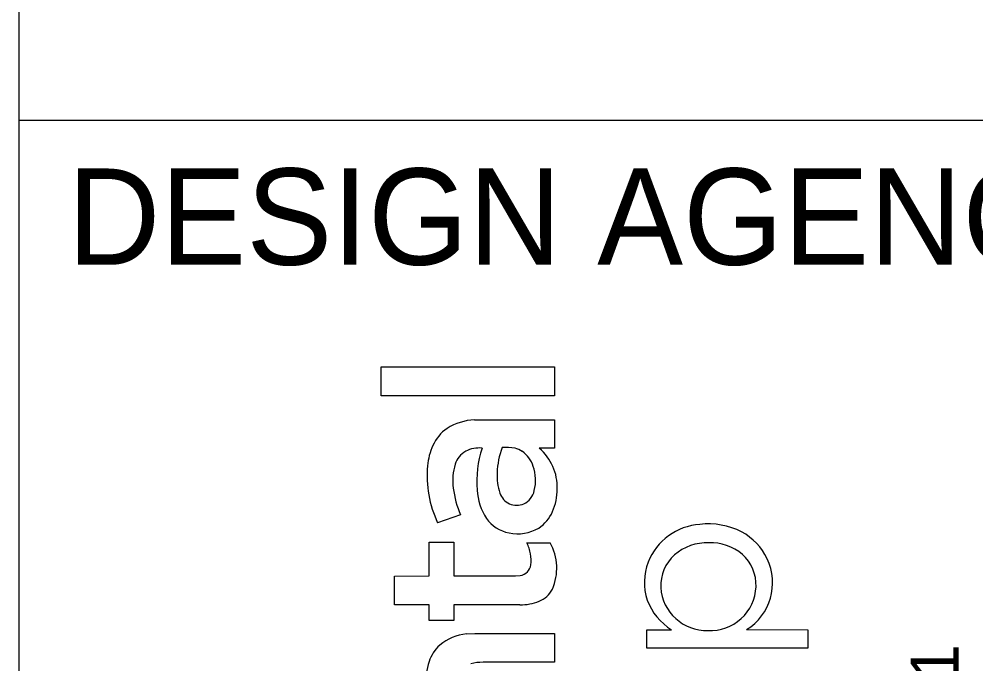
# Model space of a CAD drawing. Extents: x -6.7 to 34, y -1.6 to 22.
# Drawn here: x 32 to 32.993, y 4.436 to 5.105 of the extents above; entities that cross this region are included whole.
import ezdxf

# ---------------------------------------------------------------- set-up
doc = ezdxf.new("R2010")
doc.units = 0
doc.layers.add('SH_Border', color=7, linetype='Continuous')
doc.layers.add('SH_Cut_Line', color=7, linetype='Continuous')

msp = doc.modelspace()

# ---------------------------------------------------------------- linework, layer by layer
at = {"layer": 'SH_Border'}
for p, q in [((32, 0.5), (32, 21.5)), ((32, 5), (33.5, 5))]:
    msp.add_line(p, q, dxfattribs=at)
at = {"layer": 'SH_Cut_Line'}
for p, q in [((32.37557, 4.71411), (32.37557, 4.74397)), ((32.37557, 4.74397), (32.55571, 4.74397)), ((32.55571, 4.74397), (32.55571, 4.71411)), ((32.55571, 4.71411), (32.37557, 4.71411)), ((32.47265, 4.68899), (32.55553, 4.68918)), ((32.55553, 4.68918), (32.55571, 4.65956)), ((32.55571, 4.65956), (32.53971, 4.65956)), ((32.45818, 4.59045), (32.43431, 4.58233)), ((32.42542, 4.52705), (32.42548, 4.56209)), ((32.42548, 4.56209), (32.45108, 4.56209)), ((32.45108, 4.56209), (32.45117, 4.52705)), ((32.52695, 4.56159), (32.5511, 4.56159)), ((32.51498, 4.52705), (32.52005, 4.52749)), ((32.38964, 4.52701), (32.42542, 4.52705)), ((32.38964, 4.49719), (32.38964, 4.52701)), ((32.45117, 4.52705), (32.51498, 4.52705)), ((32.42542, 4.49717), (32.38964, 4.49719)), ((32.42542, 4.48067), (32.42542, 4.49717)), ((32.51969, 4.49718), (32.45108, 4.49715)), ((32.45108, 4.49715), (32.45108, 4.48066)), ((32.45108, 4.48066), (32.42542, 4.48067)), ((32.65152, 4.47113), (32.67709, 4.47115)), ((32.65152, 4.45215), (32.65152, 4.47113)), ((32.75491, 4.47132), (32.81858, 4.47108)), ((32.81858, 4.47108), (32.81843, 4.45215)), ((32.46439, 4.46686), (32.47289, 4.46732)), ((32.47289, 4.46732), (32.55571, 4.46732)), ((32.55571, 4.46732), (32.55571, 4.43753)), ((32.81843, 4.45215), (32.65152, 4.45215)), ((32.55571, 4.43753), (32.4814, 4.43746))]:
    msp.add_line(p, q, dxfattribs=at)
msp.add_lwpolyline([(32.37557, 4.71411), (32.37557, 4.74397), (32.55571, 4.74397), (32.55571, 4.71411)], close=True, dxfattribs=at)
for points in [[(32.47265, 4.68899), (32.55553, 4.68918), (32.55571, 4.65956)], [(32.55571, 4.65956), (32.53971, 4.65956)], [(32.45818, 4.59045), (32.43431, 4.58233)], [(32.51969, 4.49718), (32.45108, 4.49715), (32.45108, 4.48066), (32.42542, 4.48067), (32.42542, 4.49717), (32.38964, 4.49719), (32.38964, 4.52701), (32.42542, 4.52705), (32.42548, 4.56209), (32.45108, 4.56209), (32.45117, 4.52705), (32.51498, 4.52705), (32.52005, 4.52749)], [(32.52695, 4.56159), (32.5511, 4.56159)], [(32.75491, 4.47132), (32.81858, 4.47108), (32.81843, 4.45215), (32.65152, 4.45215)], [(32.65152, 4.45215), (32.65152, 4.47113), (32.67709, 4.47115)], [(32.46439, 4.46686), (32.47289, 4.46732), (32.55571, 4.46732), (32.55571, 4.43753), (32.4814, 4.43746)]]:
    msp.add_lwpolyline(points, dxfattribs=at)
for centre, radius, start, end in [((32.47452, 4.63256), 0.05646, 91.89422, 122.63175), ((32.47452, 4.63256), 0.05646, 91.89422, 122.63175), ((32.46847, 4.64467), 0.04302, 124.53704, 155.65938), ((32.46847, 4.64467), 0.04302, 124.53704, 155.65938), ((32.48824, 4.63612), 0.06457, 155.9764, 175.31491), ((32.48824, 4.63612), 0.06457, 155.9764, 175.31491), ((32.47786, 4.62778), 0.03213, 85.38017, 116.62224), ((32.47786, 4.62778), 0.03213, 85.38017, 116.62224), ((32.58787, 4.62508), 0.1129, 162.08213, 184.52847), ((32.58787, 4.62508), 0.1129, 162.08213, 184.52847), ((32.58013, 4.63131), 0.08411, 159.83657, 178.03621), ((32.58013, 4.63131), 0.08411, 159.83657, 178.03621), ((32.50509, 4.60743), 0.05302, 79.66963, 94.23216), ((32.50509, 4.60743), 0.05302, 79.66963, 94.23216), ((32.50892, 4.63643), 0.02384, 56.89129, 76.21489), ((32.50892, 4.63643), 0.02384, 56.89129, 76.21489), ((32.50551, 4.61914), 0.05295, 358.07459, 49.76196), ((32.50551, 4.61914), 0.05295, 358.07459, 49.76196), ((32.47525, 4.6356), 0.024, 119.42515, 161.66285), ((32.47525, 4.6356), 0.024, 119.42515, 161.66285), ((32.5052, 4.63184), 0.02973, 17.59837, 55.72819), ((32.5052, 4.63184), 0.02973, 17.59837, 55.72819), ((32.53639, 4.63078), 0.113, 174.61011, 205.38987), ((32.53639, 4.63078), 0.113, 174.61011, 205.38987), ((32.50758, 4.62645), 0.05758, 163.13694, 188.16749), ((32.50758, 4.62645), 0.05758, 163.13694, 188.16749), ((32.4916, 4.6264), 0.04435, 345.94084, 18.99188), ((32.4916, 4.6264), 0.04435, 345.94084, 18.99188), ((32.54655, 4.6303), 0.05063, 175.59026, 199.88569), ((32.54655, 4.6303), 0.05063, 175.59026, 199.88569), ((32.54725, 4.62973), 0.09735, 186.75982, 203.79807), ((32.54725, 4.62973), 0.09735, 186.75982, 203.79807), ((32.50187, 4.61678), 0.05657, 336.01604, 0.59505), ((32.50187, 4.61678), 0.05657, 336.01604, 0.59505), ((32.53279, 4.61874), 0.05752, 182.56764, 213.71437), ((32.53279, 4.61874), 0.05752, 182.56764, 213.71437), ((32.51642, 4.61886), 0.01841, 198.28436, 293.30806), ((32.51642, 4.61886), 0.01841, 198.28436, 293.30806), ((32.51521, 4.61994), 0.01989, 295.28829, 347.46387), ((32.51521, 4.61994), 0.01989, 295.28829, 347.46387), ((32.51752, 4.60969), 0.03938, 303.44357, 336.18), ((32.51752, 4.60969), 0.03938, 303.44357, 336.18), ((32.51487, 4.60782), 0.03656, 215.06685, 259.81327), ((32.51487, 4.60782), 0.03656, 215.06685, 259.81327), ((32.71081, 4.51825), 0.06243, 93.98662, 158.31194), ((32.71081, 4.51825), 0.06243, 93.98662, 158.31194), ((32.71557, 4.5065), 0.07459, 62.68889, 97.01346), ((32.71557, 4.5065), 0.07459, 62.68889, 97.01346), ((32.51753, 4.6131), 0.04227, 257.52557, 300.88195), ((32.51753, 4.6131), 0.04227, 257.52557, 300.88195), ((32.72123, 4.51914), 0.06076, 25.06574, 61.96022), ((32.72123, 4.51914), 0.06076, 25.06574, 61.96022), ((32.48625, 4.54199), 0.04518, 10.15449, 25.72303), ((32.48625, 4.54199), 0.04518, 10.15449, 25.72303), ((32.50302, 4.53506), 0.05491, 336.58903, 28.89913), ((32.50302, 4.53506), 0.05491, 336.58903, 28.89913), ((32.71379, 4.51017), 0.05134, 87.89653, 131.18123), ((32.71379, 4.51017), 0.05134, 87.89653, 131.18123), ((32.7175, 4.51023), 0.05127, 49.90886, 92.03625), ((32.7175, 4.51023), 0.05127, 49.90886, 92.03625), ((32.49573, 4.54365), 0.03556, 351.91398, 10.20594), ((32.49573, 4.54365), 0.03556, 351.91398, 10.20594), ((32.7092, 4.51674), 0.04338, 132.32887, 182.09489), ((32.7092, 4.51674), 0.04338, 132.32887, 182.09489), ((32.72154, 4.51733), 0.04327, 358.04871, 47.94467), ((32.72154, 4.51733), 0.04327, 358.04871, 47.94467), ((32.51837, 4.54001), 0.01263, 277.61423, 353.79181), ((32.51837, 4.54001), 0.01263, 277.61423, 353.79181), ((32.70695, 4.52016), 0.05815, 158.65601, 198.17101), ((32.70695, 4.52016), 0.05815, 158.65601, 198.17101), ((32.7245, 4.52004), 0.05743, 301.97764, 25.64176), ((32.7245, 4.52004), 0.05743, 301.97764, 25.64176), ((32.52913, 4.52612), 0.02749, 292.68889, 332.05977), ((32.52913, 4.52612), 0.02749, 292.68889, 332.05977), ((32.71352, 4.51815), 0.04776, 183.59741, 271.7045), ((32.71352, 4.51815), 0.04776, 183.59741, 271.7045), ((32.71717, 4.51801), 0.04766, 267.31494, 357.4019), ((32.71717, 4.51801), 0.04766, 267.31494, 357.4019), ((32.52088, 4.54856), 0.05139, 268.67266, 291.52354), ((32.52088, 4.54856), 0.05139, 268.67266, 291.52354), ((32.7103, 4.52433), 0.0627, 200.83985, 238.01619), ((32.7103, 4.52433), 0.0627, 200.83985, 238.01619), ((32.46871, 4.41716), 0.04988, 94.97056, 130.22484), ((32.46871, 4.41716), 0.04988, 94.97056, 130.22484), ((32.46348, 4.42551), 0.04016, 132.22383, 161.68229), ((32.46348, 4.42551), 0.04016, 132.22383, 161.68229), ((32.47872, 4.42108), 0.05602, 162.27398, 187.79173), ((32.47872, 4.42108), 0.05602, 162.27398, 187.79173), ((32.48108, 4.39145), 0.04601, 89.60515, 105.33026), ((32.48108, 4.39145), 0.04601, 89.60515, 105.33026)]:
    msp.add_arc(centre, radius, start, end, dxfattribs=at)

# ---------------------------------------------------------------- texts
msp.add_text('DESIGN AGENCY', height=0.1, dxfattribs=at).set_placement((32.05, 4.85))
msp.add_text('450 GRANT ST., AKRON, OH  44311', height=0.0498462, rotation=90, dxfattribs=at).set_placement((32.97489, 3.33738))

doc.saveas('drawing.dxf')
